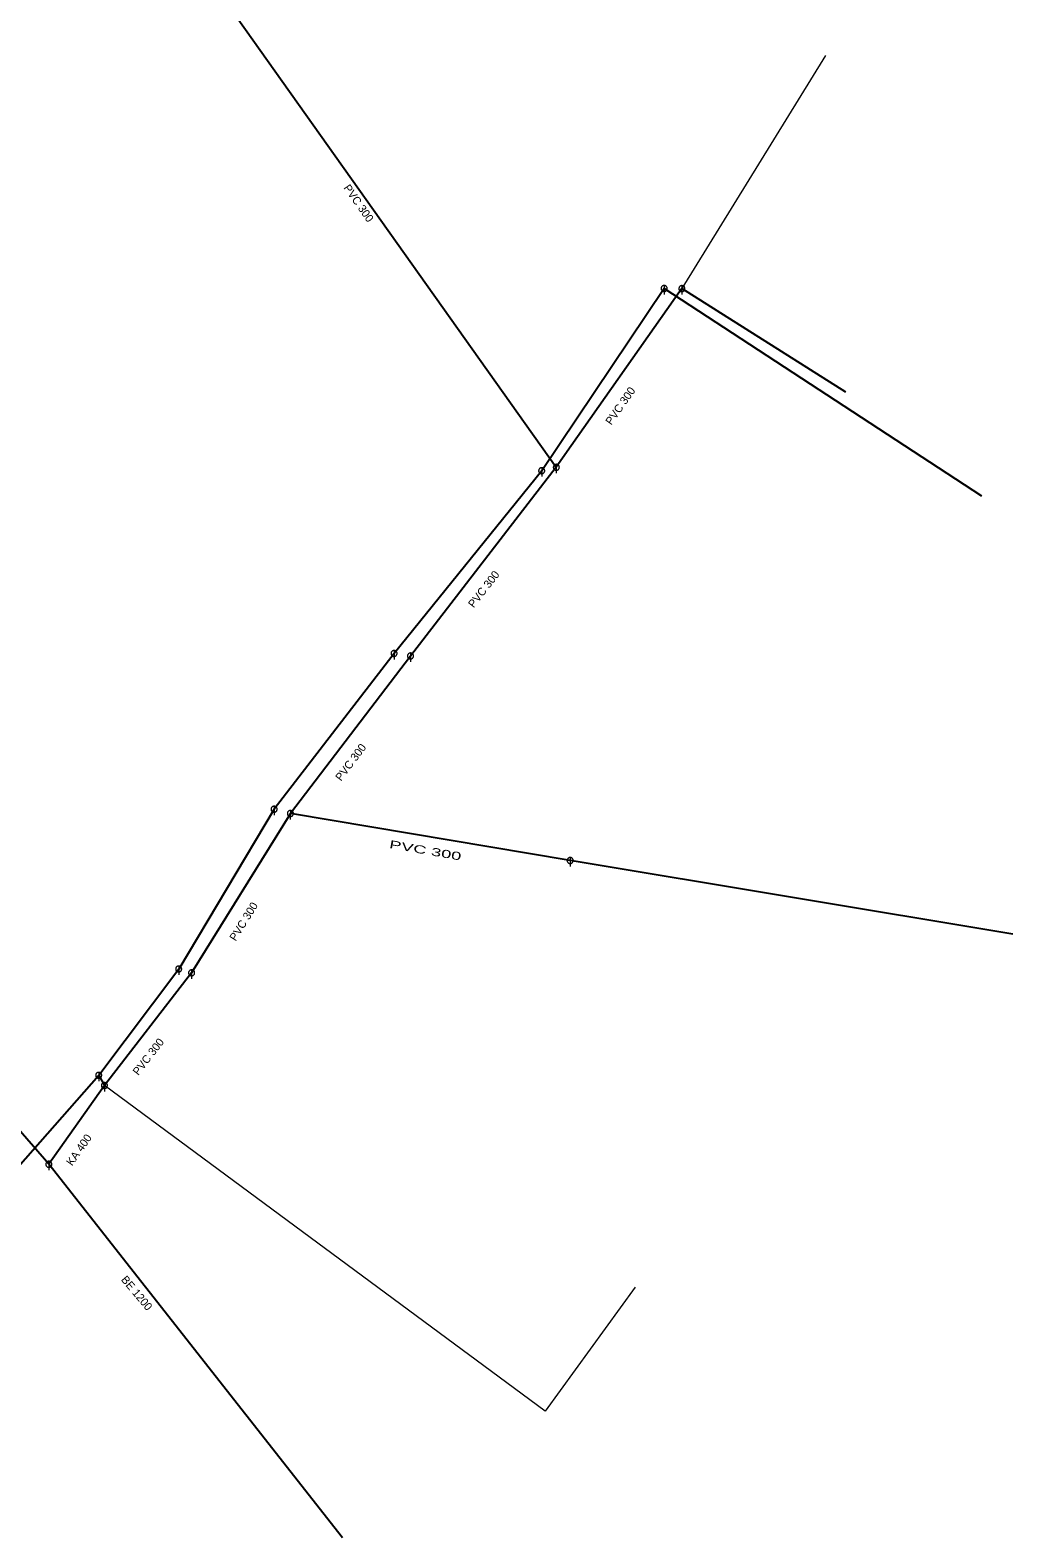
# Model space of a CAD drawing. Extents: x -687468 to -685917, y -974192 to -973456.
# Drawn here: x -686039.1 to -685957.2, y -974082.7 to -973957.1 of the extents above; entities that cross this region are included whole.
import ezdxf
from ezdxf.enums import TextEntityAlignment as Align

# ---------------------------------------------------------------- set-up
doc = ezdxf.new("R2010")
doc.units = 0
doc.header["$LTSCALE"] = 0.27
for name, color, linetype, lineweight in [('1', 7, 'Continuous', 13), ('11', 7, 'Continuous', 13), ('14', 7, 'Continuous', 25), ('22', 7, 'Continuous', 13)]:
    doc.layers.add(name, color=color, linetype=linetype, lineweight=lineweight)

msp = doc.modelspace()

# ---------------------------------------------------------------- linework, layer by layer
at = {"layer": '11'}
for p, q in [((-685972.831, -973959.254), (-685984.8, -973978.673)), ((-685996.186, -974072.171), (-686032.918, -974045.045)), ((-685988.697, -974061.827), (-685996.186, -974072.171))]:
    msp.add_line(p, q, dxfattribs=at)
at = {"layer": '14'}
for p, q in [((-686024.619, -973952.22), (-685995.262, -973993.552)), ((-685984.8, -973978.673), (-685995.262, -973993.552)), ((-685959.797, -973995.951), (-685986.275, -973978.656)), ((-685971.129, -973987.287), (-685984.8, -973978.673)), ((-685995.262, -973993.552), (-686007.415, -974009.269)), ((-686007.415, -974009.269), (-686017.42, -974022.389)), ((-686037.548, -974051.599), (-686065.207, -974019.789)), ((-686017.42, -974022.389), (-686025.649, -974035.655)), ((-685994.107, -974026.299), (-686017.42, -974022.389)), ((-685957.222, -974032.43), (-685994.107, -974026.299)), ((-686025.649, -974035.655), (-686032.918, -974045.045)), ((-686033.39, -974044.195), (-686049.981, -974063.058)), ((-686032.918, -974045.045), (-686037.548, -974051.599)), ((-686013.085, -974082.714), (-686037.548, -974051.599))]:
    msp.add_line(p, q, dxfattribs=at)
for points in [[(-685986.275, -973978.656), (-685996.482, -973993.837), (-686008.783, -974009.058), (-686018.78, -974022.032), (-686026.725, -974035.34)], [(-686026.725, -974035.34), (-686033.39, -974044.195), (-686032.918, -974045.045)]]:
    msp.add_lwpolyline(points, dxfattribs=at)
at = {"layer": '22'}
for p, q in [((-685986.274, -973978.404), (-685986.275, -973979.147)), ((-685984.799, -973978.421), (-685984.8, -973979.164)), ((-685996.481, -973993.585), (-685996.482, -973994.329)), ((-685995.261, -973993.3), (-685995.262, -973994.044)), ((-686008.782, -974008.806), (-686008.783, -974009.549)), ((-686007.414, -974009.017), (-686007.415, -974009.761)), ((-686018.779, -974021.78), (-686018.78, -974022.524)), ((-686017.416, -974022.137), (-686017.427, -974022.88)), ((-685994.106, -974026.047), (-685994.107, -974026.791)), ((-686026.724, -974035.088), (-686026.725, -974035.831)), ((-686025.648, -974035.403), (-686025.649, -974036.147)), ((-686033.389, -974043.943), (-686033.39, -974044.686)), ((-686032.917, -974044.793), (-686032.918, -974045.537)), ((-686037.547, -974051.347), (-686037.548, -974052.091))]:
    msp.add_line(p, q, dxfattribs=at)
for points in [[(-685986.023, -973978.656), (-685986.024, -973978.63), (-685986.028, -973978.604), (-685986.034, -973978.578), (-685986.044, -973978.554), (-685986.056, -973978.53), (-685986.07, -973978.508), (-685986.087, -973978.487), (-685986.105, -973978.469), (-685986.126, -973978.452), (-685986.148, -973978.438), (-685986.172, -973978.426), (-685986.196, -973978.416), (-685986.222, -973978.41), (-685986.248, -973978.406), (-685986.274, -973978.404), (-685986.3, -973978.405), (-685986.326, -973978.409), (-685986.352, -973978.415), (-685986.377, -973978.425), (-685986.4, -973978.437), (-685986.422, -973978.451), (-685986.443, -973978.468), (-685986.461, -973978.486), (-685986.478, -973978.507), (-685986.492, -973978.529), (-685986.504, -973978.553), (-685986.514, -973978.577), (-685986.521, -973978.603), (-685986.525, -973978.629), (-685986.527, -973978.655), (-685986.526, -973978.681), (-685986.522, -973978.707), (-685986.515, -973978.733), (-685986.505, -973978.758), (-685986.493, -973978.781), (-685986.479, -973978.803), (-685986.462, -973978.824), (-685986.444, -973978.842), (-685986.423, -973978.859), (-685986.401, -973978.873), (-685986.378, -973978.885), (-685986.353, -973978.895), (-685986.327, -973978.902), (-685986.301, -973978.906), (-685986.275, -973978.907), (-685986.249, -973978.907), (-685986.223, -973978.903), (-685986.197, -973978.896), (-685986.173, -973978.886), (-685986.149, -973978.874), (-685986.127, -973978.86), (-685986.106, -973978.843), (-685986.088, -973978.825), (-685986.071, -973978.804), (-685986.057, -973978.782), (-685986.045, -973978.759), (-685986.035, -973978.734), (-685986.029, -973978.708), (-685986.025, -973978.682)], [(-685984.548, -973978.673), (-685984.549, -973978.647), (-685984.553, -973978.621), (-685984.559, -973978.595), (-685984.569, -973978.571), (-685984.581, -973978.547), (-685984.595, -973978.525), (-685984.612, -973978.504), (-685984.63, -973978.486), (-685984.651, -973978.469), (-685984.673, -973978.455), (-685984.697, -973978.443), (-685984.721, -973978.433), (-685984.747, -973978.427), (-685984.773, -973978.423), (-685984.799, -973978.421), (-685984.825, -973978.422), (-685984.851, -973978.426), (-685984.877, -973978.432), (-685984.902, -973978.442), (-685984.925, -973978.454), (-685984.947, -973978.468), (-685984.968, -973978.485), (-685984.986, -973978.503), (-685985.003, -973978.524), (-685985.017, -973978.546), (-685985.029, -973978.57), (-685985.039, -973978.594), (-685985.046, -973978.62), (-685985.05, -973978.646), (-685985.052, -973978.672), (-685985.051, -973978.698), (-685985.047, -973978.724), (-685985.04, -973978.75), (-685985.03, -973978.775), (-685985.018, -973978.798), (-685985.004, -973978.82), (-685984.987, -973978.841), (-685984.969, -973978.859), (-685984.948, -973978.876), (-685984.926, -973978.89), (-685984.903, -973978.902), (-685984.878, -973978.912), (-685984.852, -973978.919), (-685984.826, -973978.923), (-685984.8, -973978.924), (-685984.774, -973978.924), (-685984.748, -973978.92), (-685984.722, -973978.913), (-685984.698, -973978.903), (-685984.674, -973978.891), (-685984.652, -973978.877), (-685984.631, -973978.86), (-685984.613, -973978.842), (-685984.596, -973978.821), (-685984.582, -973978.799), (-685984.57, -973978.776), (-685984.56, -973978.751), (-685984.554, -973978.725), (-685984.55, -973978.699)], [(-685996.23, -973993.837), (-685996.231, -973993.811), (-685996.235, -973993.785), (-685996.241, -973993.759), (-685996.251, -973993.735), (-685996.263, -973993.711), (-685996.277, -973993.689), (-685996.294, -973993.668), (-685996.312, -973993.65), (-685996.333, -973993.633), (-685996.355, -973993.619), (-685996.379, -973993.607), (-685996.403, -973993.597), (-685996.429, -973993.591), (-685996.455, -973993.587), (-685996.481, -973993.585), (-685996.507, -973993.586), (-685996.533, -973993.59), (-685996.559, -973993.596), (-685996.584, -973993.606), (-685996.607, -973993.618), (-685996.629, -973993.632), (-685996.65, -973993.649), (-685996.668, -973993.667), (-685996.685, -973993.688), (-685996.699, -973993.71), (-685996.711, -973993.734), (-685996.721, -973993.758), (-685996.728, -973993.784), (-685996.732, -973993.81), (-685996.733, -973993.836), (-685996.733, -973993.862), (-685996.729, -973993.888), (-685996.722, -973993.914), (-685996.712, -973993.939), (-685996.7, -973993.962), (-685996.686, -973993.984), (-685996.669, -973994.005), (-685996.651, -973994.023), (-685996.63, -973994.04), (-685996.608, -973994.054), (-685996.585, -973994.066), (-685996.56, -973994.076), (-685996.534, -973994.083), (-685996.508, -973994.087), (-685996.482, -973994.089), (-685996.456, -973994.088), (-685996.43, -973994.084), (-685996.404, -973994.077), (-685996.38, -973994.067), (-685996.356, -973994.055), (-685996.334, -973994.041), (-685996.313, -973994.024), (-685996.295, -973994.006), (-685996.278, -973993.985), (-685996.264, -973993.963), (-685996.252, -973993.94), (-685996.242, -973993.915), (-685996.236, -973993.889), (-685996.232, -973993.863)], [(-685995.01, -973993.552), (-685995.011, -973993.526), (-685995.015, -973993.5), (-685995.021, -973993.474), (-685995.031, -973993.45), (-685995.043, -973993.426), (-685995.057, -973993.404), (-685995.074, -973993.383), (-685995.092, -973993.365), (-685995.113, -973993.348), (-685995.135, -973993.334), (-685995.159, -973993.322), (-685995.183, -973993.312), (-685995.209, -973993.306), (-685995.235, -973993.302), (-685995.261, -973993.3), (-685995.287, -973993.301), (-685995.313, -973993.305), (-685995.339, -973993.311), (-685995.364, -973993.321), (-685995.387, -973993.333), (-685995.409, -973993.347), (-685995.43, -973993.364), (-685995.448, -973993.382), (-685995.465, -973993.403), (-685995.479, -973993.425), (-685995.491, -973993.449), (-685995.501, -973993.473), (-685995.508, -973993.499), (-685995.512, -973993.525), (-685995.514, -973993.551), (-685995.513, -973993.577), (-685995.509, -973993.603), (-685995.502, -973993.629), (-685995.492, -973993.654), (-685995.48, -973993.677), (-685995.466, -973993.699), (-685995.449, -973993.72), (-685995.431, -973993.738), (-685995.41, -973993.755), (-685995.388, -973993.769), (-685995.365, -973993.781), (-685995.34, -973993.791), (-685995.314, -973993.798), (-685995.288, -973993.802), (-685995.262, -973993.804), (-685995.236, -973993.803), (-685995.21, -973993.799), (-685995.184, -973993.792), (-685995.16, -973993.782), (-685995.136, -973993.77), (-685995.114, -973993.756), (-685995.093, -973993.739), (-685995.075, -973993.721), (-685995.058, -973993.7), (-685995.044, -973993.678), (-685995.032, -973993.655), (-685995.022, -973993.63), (-685995.016, -973993.604), (-685995.012, -973993.578)], [(-686008.531, -974009.058), (-686008.532, -974009.032), (-686008.536, -974009.006), (-686008.542, -974008.98), (-686008.552, -974008.956), (-686008.564, -974008.932), (-686008.578, -974008.91), (-686008.595, -974008.889), (-686008.613, -974008.871), (-686008.634, -974008.854), (-686008.656, -974008.84), (-686008.68, -974008.828), (-686008.704, -974008.818), (-686008.73, -974008.812), (-686008.756, -974008.808), (-686008.782, -974008.806), (-686008.808, -974008.807), (-686008.834, -974008.811), (-686008.86, -974008.817), (-686008.885, -974008.827), (-686008.908, -974008.839), (-686008.93, -974008.853), (-686008.951, -974008.87), (-686008.969, -974008.888), (-686008.986, -974008.909), (-686009, -974008.931), (-686009.012, -974008.955), (-686009.022, -974008.979), (-686009.029, -974009.005), (-686009.033, -974009.031), (-686009.035, -974009.057), (-686009.034, -974009.083), (-686009.03, -974009.109), (-686009.023, -974009.135), (-686009.013, -974009.16), (-686009.001, -974009.183), (-686008.987, -974009.205), (-686008.97, -974009.226), (-686008.952, -974009.244), (-686008.931, -974009.261), (-686008.909, -974009.275), (-686008.886, -974009.287), (-686008.861, -974009.297), (-686008.835, -974009.304), (-686008.809, -974009.308), (-686008.783, -974009.309), (-686008.757, -974009.309), (-686008.731, -974009.305), (-686008.705, -974009.298), (-686008.681, -974009.288), (-686008.657, -974009.276), (-686008.635, -974009.262), (-686008.614, -974009.245), (-686008.596, -974009.227), (-686008.579, -974009.206), (-686008.565, -974009.184), (-686008.553, -974009.161), (-686008.543, -974009.136), (-686008.537, -974009.11), (-686008.533, -974009.084)], [(-686007.163, -974009.269), (-686007.164, -974009.243), (-686007.168, -974009.217), (-686007.174, -974009.191), (-686007.184, -974009.167), (-686007.196, -974009.143), (-686007.21, -974009.121), (-686007.227, -974009.1), (-686007.245, -974009.082), (-686007.266, -974009.065), (-686007.288, -974009.051), (-686007.312, -974009.039), (-686007.336, -974009.029), (-686007.362, -974009.023), (-686007.388, -974009.019), (-686007.414, -974009.017), (-686007.44, -974009.018), (-686007.466, -974009.022), (-686007.492, -974009.028), (-686007.517, -974009.038), (-686007.54, -974009.05), (-686007.562, -974009.064), (-686007.583, -974009.081), (-686007.601, -974009.099), (-686007.618, -974009.12), (-686007.632, -974009.142), (-686007.644, -974009.166), (-686007.654, -974009.19), (-686007.661, -974009.216), (-686007.665, -974009.242), (-686007.667, -974009.268), (-686007.666, -974009.294), (-686007.662, -974009.32), (-686007.655, -974009.346), (-686007.645, -974009.371), (-686007.633, -974009.394), (-686007.619, -974009.416), (-686007.602, -974009.437), (-686007.584, -974009.455), (-686007.563, -974009.472), (-686007.541, -974009.486), (-686007.518, -974009.498), (-686007.493, -974009.508), (-686007.467, -974009.515), (-686007.441, -974009.519), (-686007.415, -974009.521), (-686007.389, -974009.52), (-686007.363, -974009.516), (-686007.337, -974009.509), (-686007.313, -974009.499), (-686007.289, -974009.487), (-686007.267, -974009.473), (-686007.246, -974009.456), (-686007.228, -974009.438), (-686007.211, -974009.417), (-686007.197, -974009.395), (-686007.185, -974009.372), (-686007.175, -974009.347), (-686007.169, -974009.321), (-686007.165, -974009.295)], [(-686018.528, -974022.032), (-686018.529, -974022.006), (-686018.533, -974021.98), (-686018.539, -974021.954), (-686018.549, -974021.93), (-686018.561, -974021.906), (-686018.575, -974021.884), (-686018.592, -974021.863), (-686018.61, -974021.845), (-686018.631, -974021.828), (-686018.653, -974021.814), (-686018.677, -974021.802), (-686018.701, -974021.792), (-686018.727, -974021.786), (-686018.753, -974021.782), (-686018.779, -974021.78), (-686018.805, -974021.781), (-686018.831, -974021.785), (-686018.857, -974021.791), (-686018.882, -974021.801), (-686018.905, -974021.813), (-686018.927, -974021.827), (-686018.948, -974021.844), (-686018.966, -974021.862), (-686018.983, -974021.883), (-686018.997, -974021.905), (-686019.009, -974021.929), (-686019.019, -974021.953), (-686019.026, -974021.979), (-686019.03, -974022.005), (-686019.032, -974022.031), (-686019.031, -974022.057), (-686019.027, -974022.083), (-686019.02, -974022.109), (-686019.01, -974022.134), (-686018.998, -974022.157), (-686018.984, -974022.179), (-686018.967, -974022.2), (-686018.949, -974022.218), (-686018.928, -974022.235), (-686018.906, -974022.249), (-686018.883, -974022.261), (-686018.858, -974022.271), (-686018.832, -974022.278), (-686018.806, -974022.282), (-686018.78, -974022.284), (-686018.754, -974022.283), (-686018.728, -974022.279), (-686018.702, -974022.272), (-686018.678, -974022.262), (-686018.654, -974022.25), (-686018.632, -974022.236), (-686018.611, -974022.219), (-686018.593, -974022.201), (-686018.576, -974022.18), (-686018.562, -974022.158), (-686018.55, -974022.135), (-686018.54, -974022.11), (-686018.534, -974022.084), (-686018.53, -974022.058)], [(-686017.168, -974022.392), (-686017.169, -974022.366), (-686017.173, -974022.34), (-686017.178, -974022.314), (-686017.188, -974022.29), (-686017.2, -974022.266), (-686017.213, -974022.244), (-686017.23, -974022.222), (-686017.248, -974022.204), (-686017.268, -974022.187), (-686017.29, -974022.173), (-686017.314, -974022.16), (-686017.338, -974022.15), (-686017.364, -974022.143), (-686017.39, -974022.139), (-686017.416, -974022.137), (-686017.442, -974022.138), (-686017.468, -974022.142), (-686017.494, -974022.147), (-686017.519, -974022.157), (-686017.542, -974022.169), (-686017.564, -974022.182), (-686017.586, -974022.199), (-686017.604, -974022.217), (-686017.621, -974022.237), (-686017.635, -974022.259), (-686017.648, -974022.283), (-686017.658, -974022.307), (-686017.666, -974022.333), (-686017.67, -974022.359), (-686017.671, -974022.385), (-686017.671, -974022.411), (-686017.667, -974022.437), (-686017.661, -974022.463), (-686017.651, -974022.488), (-686017.639, -974022.511), (-686017.626, -974022.533), (-686017.609, -974022.555), (-686017.591, -974022.573), (-686017.571, -974022.59), (-686017.549, -974022.604), (-686017.526, -974022.617), (-686017.501, -974022.627), (-686017.475, -974022.635), (-686017.449, -974022.639), (-686017.423, -974022.64), (-686017.397, -974022.64), (-686017.371, -974022.636), (-686017.345, -974022.63), (-686017.321, -974022.62), (-686017.297, -974022.608), (-686017.275, -974022.595), (-686017.253, -974022.578), (-686017.235, -974022.56), (-686017.218, -974022.54), (-686017.204, -974022.518), (-686017.191, -974022.495), (-686017.181, -974022.47), (-686017.174, -974022.444), (-686017.17, -974022.418)], [(-685993.855, -974026.299), (-685993.856, -974026.273), (-685993.86, -974026.247), (-685993.866, -974026.221), (-685993.876, -974026.197), (-685993.888, -974026.173), (-685993.902, -974026.151), (-685993.919, -974026.13), (-685993.937, -974026.112), (-685993.958, -974026.095), (-685993.98, -974026.081), (-685994.004, -974026.069), (-685994.028, -974026.059), (-685994.054, -974026.053), (-685994.08, -974026.049), (-685994.106, -974026.047), (-685994.132, -974026.048), (-685994.158, -974026.052), (-685994.184, -974026.058), (-685994.209, -974026.068), (-685994.232, -974026.08), (-685994.254, -974026.094), (-685994.275, -974026.111), (-685994.293, -974026.129), (-685994.31, -974026.15), (-685994.324, -974026.172), (-685994.336, -974026.196), (-685994.346, -974026.22), (-685994.353, -974026.246), (-685994.357, -974026.272), (-685994.358, -974026.298), (-685994.358, -974026.324), (-685994.354, -974026.35), (-685994.347, -974026.376), (-685994.337, -974026.401), (-685994.325, -974026.424), (-685994.311, -974026.446), (-685994.294, -974026.467), (-685994.276, -974026.485), (-685994.255, -974026.502), (-685994.233, -974026.516), (-685994.21, -974026.528), (-685994.185, -974026.538), (-685994.159, -974026.545), (-685994.133, -974026.549), (-685994.107, -974026.551), (-685994.081, -974026.55), (-685994.055, -974026.546), (-685994.029, -974026.539), (-685994.005, -974026.529), (-685993.981, -974026.517), (-685993.959, -974026.503), (-685993.938, -974026.486), (-685993.92, -974026.468), (-685993.903, -974026.447), (-685993.889, -974026.425), (-685993.877, -974026.402), (-685993.867, -974026.377), (-685993.861, -974026.351), (-685993.857, -974026.325)], [(-686026.473, -974035.34), (-686026.474, -974035.314), (-686026.478, -974035.288), (-686026.484, -974035.262), (-686026.494, -974035.238), (-686026.506, -974035.214), (-686026.52, -974035.192), (-686026.537, -974035.171), (-686026.555, -974035.153), (-686026.576, -974035.136), (-686026.598, -974035.122), (-686026.622, -974035.11), (-686026.646, -974035.1), (-686026.672, -974035.094), (-686026.698, -974035.09), (-686026.724, -974035.088), (-686026.75, -974035.089), (-686026.776, -974035.093), (-686026.802, -974035.099), (-686026.827, -974035.109), (-686026.85, -974035.121), (-686026.872, -974035.135), (-686026.893, -974035.152), (-686026.911, -974035.17), (-686026.928, -974035.191), (-686026.942, -974035.213), (-686026.954, -974035.237), (-686026.964, -974035.261), (-686026.971, -974035.287), (-686026.975, -974035.313), (-686026.977, -974035.339), (-686026.976, -974035.365), (-686026.972, -974035.391), (-686026.965, -974035.417), (-686026.955, -974035.442), (-686026.943, -974035.465), (-686026.929, -974035.487), (-686026.912, -974035.508), (-686026.894, -974035.526), (-686026.873, -974035.543), (-686026.851, -974035.557), (-686026.828, -974035.569), (-686026.803, -974035.579), (-686026.777, -974035.586), (-686026.751, -974035.59), (-686026.725, -974035.592), (-686026.699, -974035.591), (-686026.673, -974035.587), (-686026.647, -974035.58), (-686026.623, -974035.57), (-686026.599, -974035.558), (-686026.577, -974035.544), (-686026.556, -974035.527), (-686026.538, -974035.509), (-686026.521, -974035.488), (-686026.507, -974035.466), (-686026.495, -974035.443), (-686026.485, -974035.418), (-686026.479, -974035.392), (-686026.475, -974035.366)], [(-686025.397, -974035.655), (-686025.398, -974035.629), (-686025.402, -974035.603), (-686025.408, -974035.577), (-686025.418, -974035.553), (-686025.43, -974035.529), (-686025.444, -974035.507), (-686025.461, -974035.486), (-686025.479, -974035.468), (-686025.5, -974035.451), (-686025.522, -974035.437), (-686025.546, -974035.425), (-686025.57, -974035.415), (-686025.596, -974035.409), (-686025.622, -974035.405), (-686025.648, -974035.403), (-686025.674, -974035.404), (-686025.7, -974035.408), (-686025.726, -974035.414), (-686025.751, -974035.424), (-686025.774, -974035.436), (-686025.796, -974035.45), (-686025.817, -974035.467), (-686025.835, -974035.485), (-686025.852, -974035.506), (-686025.866, -974035.528), (-686025.878, -974035.552), (-686025.888, -974035.576), (-686025.895, -974035.602), (-686025.899, -974035.628), (-686025.901, -974035.654), (-686025.9, -974035.68), (-686025.896, -974035.706), (-686025.889, -974035.732), (-686025.879, -974035.757), (-686025.867, -974035.78), (-686025.853, -974035.802), (-686025.836, -974035.823), (-686025.818, -974035.841), (-686025.797, -974035.858), (-686025.775, -974035.872), (-686025.752, -974035.884), (-686025.727, -974035.894), (-686025.701, -974035.901), (-686025.675, -974035.905), (-686025.649, -974035.907), (-686025.623, -974035.906), (-686025.597, -974035.902), (-686025.571, -974035.895), (-686025.547, -974035.885), (-686025.523, -974035.873), (-686025.501, -974035.859), (-686025.48, -974035.842), (-686025.462, -974035.824), (-686025.445, -974035.803), (-686025.431, -974035.781), (-686025.419, -974035.758), (-686025.409, -974035.733), (-686025.403, -974035.707), (-686025.399, -974035.681)], [(-686033.138, -974044.195), (-686033.139, -974044.169), (-686033.143, -974044.143), (-686033.149, -974044.117), (-686033.159, -974044.093), (-686033.171, -974044.069), (-686033.185, -974044.047), (-686033.202, -974044.026), (-686033.22, -974044.008), (-686033.241, -974043.991), (-686033.263, -974043.977), (-686033.287, -974043.965), (-686033.311, -974043.955), (-686033.337, -974043.949), (-686033.363, -974043.945), (-686033.389, -974043.943), (-686033.415, -974043.944), (-686033.441, -974043.948), (-686033.467, -974043.954), (-686033.492, -974043.964), (-686033.515, -974043.976), (-686033.537, -974043.99), (-686033.558, -974044.007), (-686033.576, -974044.025), (-686033.593, -974044.046), (-686033.607, -974044.068), (-686033.619, -974044.092), (-686033.629, -974044.116), (-686033.636, -974044.142), (-686033.64, -974044.168), (-686033.642, -974044.194), (-686033.641, -974044.22), (-686033.637, -974044.246), (-686033.63, -974044.272), (-686033.62, -974044.297), (-686033.608, -974044.32), (-686033.594, -974044.342), (-686033.577, -974044.363), (-686033.559, -974044.381), (-686033.538, -974044.398), (-686033.516, -974044.412), (-686033.493, -974044.424), (-686033.468, -974044.434), (-686033.442, -974044.441), (-686033.416, -974044.445), (-686033.39, -974044.446), (-686033.364, -974044.446), (-686033.338, -974044.442), (-686033.312, -974044.435), (-686033.288, -974044.425), (-686033.264, -974044.413), (-686033.242, -974044.399), (-686033.221, -974044.382), (-686033.203, -974044.364), (-686033.186, -974044.343), (-686033.172, -974044.321), (-686033.16, -974044.298), (-686033.15, -974044.273), (-686033.144, -974044.247), (-686033.14, -974044.221)], [(-686032.666, -974045.045), (-686032.667, -974045.019), (-686032.671, -974044.993), (-686032.677, -974044.967), (-686032.687, -974044.943), (-686032.699, -974044.919), (-686032.713, -974044.897), (-686032.73, -974044.876), (-686032.748, -974044.858), (-686032.769, -974044.841), (-686032.791, -974044.827), (-686032.815, -974044.815), (-686032.839, -974044.805), (-686032.865, -974044.799), (-686032.891, -974044.795), (-686032.917, -974044.793), (-686032.943, -974044.794), (-686032.969, -974044.798), (-686032.995, -974044.804), (-686033.02, -974044.814), (-686033.043, -974044.826), (-686033.065, -974044.84), (-686033.086, -974044.857), (-686033.104, -974044.875), (-686033.121, -974044.896), (-686033.135, -974044.918), (-686033.147, -974044.942), (-686033.157, -974044.966), (-686033.164, -974044.992), (-686033.168, -974045.018), (-686033.169, -974045.044), (-686033.169, -974045.07), (-686033.165, -974045.096), (-686033.158, -974045.122), (-686033.148, -974045.147), (-686033.136, -974045.17), (-686033.122, -974045.192), (-686033.105, -974045.213), (-686033.087, -974045.231), (-686033.066, -974045.248), (-686033.044, -974045.262), (-686033.021, -974045.274), (-686032.996, -974045.284), (-686032.97, -974045.291), (-686032.944, -974045.295), (-686032.918, -974045.297), (-686032.892, -974045.296), (-686032.866, -974045.292), (-686032.84, -974045.285), (-686032.816, -974045.275), (-686032.792, -974045.263), (-686032.77, -974045.249), (-686032.749, -974045.232), (-686032.731, -974045.214), (-686032.714, -974045.193), (-686032.7, -974045.171), (-686032.688, -974045.148), (-686032.678, -974045.123), (-686032.672, -974045.097), (-686032.668, -974045.071)], [(-686037.296, -974051.599), (-686037.297, -974051.573), (-686037.301, -974051.547), (-686037.307, -974051.521), (-686037.317, -974051.497), (-686037.329, -974051.473), (-686037.343, -974051.451), (-686037.36, -974051.43), (-686037.378, -974051.412), (-686037.399, -974051.395), (-686037.421, -974051.381), (-686037.445, -974051.369), (-686037.469, -974051.359), (-686037.495, -974051.353), (-686037.521, -974051.349), (-686037.547, -974051.347), (-686037.573, -974051.348), (-686037.599, -974051.352), (-686037.625, -974051.358), (-686037.65, -974051.368), (-686037.673, -974051.38), (-686037.695, -974051.394), (-686037.716, -974051.411), (-686037.734, -974051.429), (-686037.751, -974051.45), (-686037.765, -974051.472), (-686037.777, -974051.496), (-686037.787, -974051.52), (-686037.794, -974051.546), (-686037.798, -974051.572), (-686037.799, -974051.598), (-686037.799, -974051.624), (-686037.795, -974051.65), (-686037.788, -974051.676), (-686037.778, -974051.701), (-686037.766, -974051.724), (-686037.752, -974051.746), (-686037.735, -974051.767), (-686037.717, -974051.785), (-686037.696, -974051.802), (-686037.674, -974051.816), (-686037.651, -974051.828), (-686037.626, -974051.838), (-686037.6, -974051.845), (-686037.574, -974051.849), (-686037.548, -974051.851), (-686037.522, -974051.85), (-686037.496, -974051.846), (-686037.47, -974051.839), (-686037.446, -974051.829), (-686037.422, -974051.817), (-686037.4, -974051.803), (-686037.379, -974051.786), (-686037.361, -974051.768), (-686037.344, -974051.747), (-686037.33, -974051.725), (-686037.318, -974051.702), (-686037.308, -974051.677), (-686037.302, -974051.651), (-686037.298, -974051.625)]]:
    msp.add_lwpolyline(points, close=True, dxfattribs=at)

# ---------------------------------------------------------------- texts
at = {"layer": '1'}
for s, rotation, p in [('PVC 300 ', 305, (-686011.932, -973971.848)), ('PVC 300 ', 55, (-685989.584, -973988.522)), ('PVC 300 ', 52, (-686000.969, -974003.808)), ('PVC 300 ', 53, (-686012.051, -974018.217)), ('PVC 300 ', 58, (-686020.967, -974031.449)), ('PVC 300 ', 52, (-686028.916, -974042.746)), ('KA 400', 55, (-686034.762, -974050.589)), ('BE 1200 ', 310, (-686030.391, -974062.637))]:
    msp.add_text(s, height=0.6667, rotation=rotation, dxfattribs=at).set_placement(p, align=Align.CENTER)
at = {"layer": '1', "width": 1.7}
msp.add_text('PVC 300 ', height=0.6667, rotation=350, dxfattribs=at).set_placement((-686006.022, -974025.815), align=Align.CENTER)

doc.saveas('drawing.dxf')
